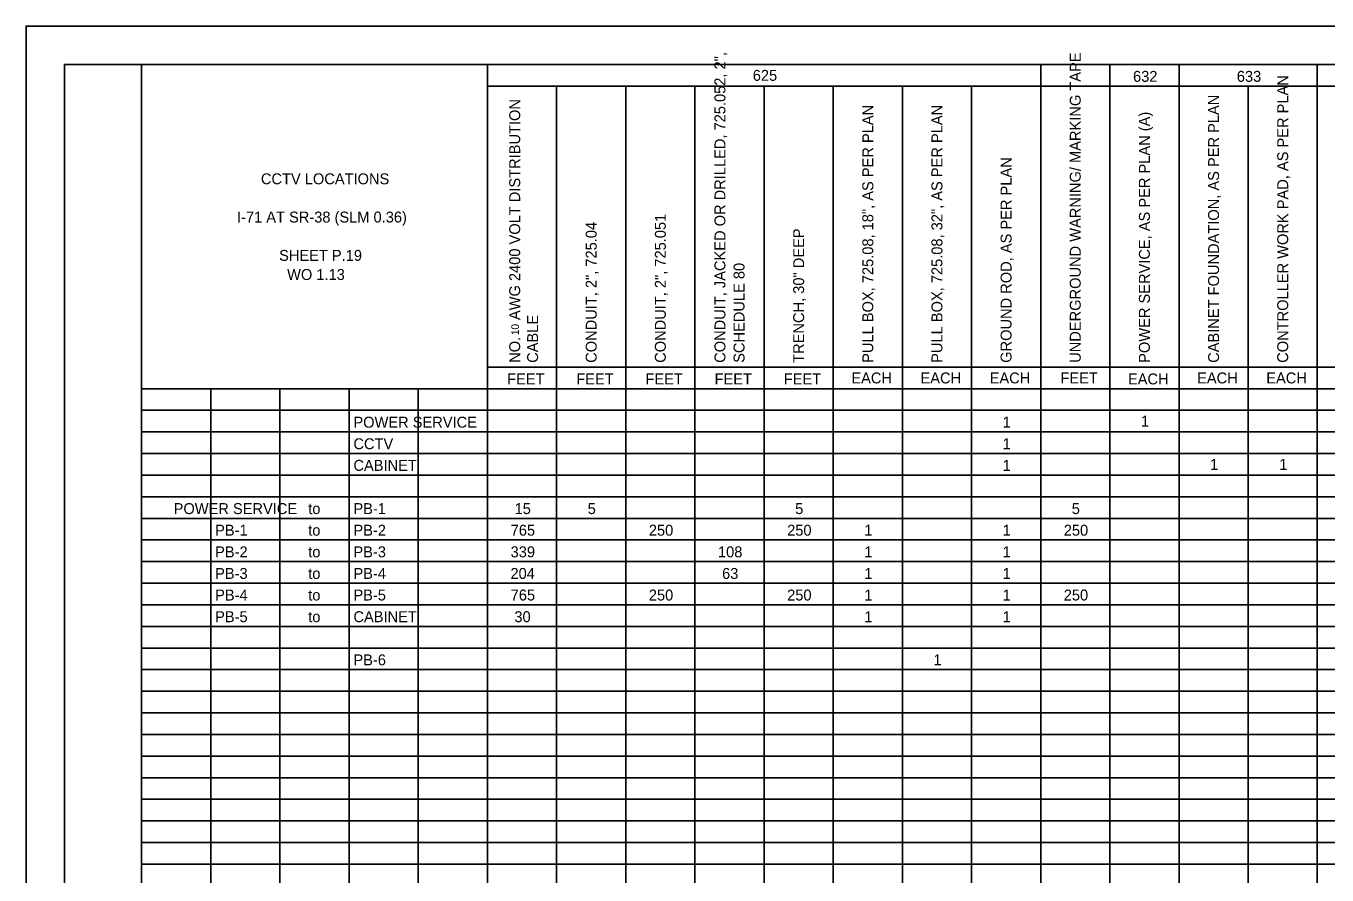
# Model space of a CAD drawing. Extents: x 0 to 34, y 0 to 22.
# Drawn here: x 0 to 16.88, y 10.99 to 22 of the extents above; entities that cross this region are included whole.
import ezdxf

# ---------------------------------------------------------------- set-up
doc = ezdxf.new("R2010")
doc.units = 0
for name, color, linetype in [('SH_Border', 7, 'Continuous'), ('SH_Cut_Line', 7, 'Continuous'), ('SH_Text', 7, 'Continuous')]:
    doc.layers.add(name, color=color, linetype=linetype)

msp = doc.modelspace()

# ---------------------------------------------------------------- linework, layer by layer
at = {"layer": 'SH_Border'}
for points in [[(0.5, 21.5), (1.5, 21.5), (1.5, 0.5), (0.5, 0.5)], [(1.5, 21.5), (33.5, 21.5), (33.5, 0.5), (1.5, 0.5)]]:
    msp.add_lwpolyline(points, close=True, dxfattribs=at)
at = {"layer": 'SH_Cut_Line'}
msp.add_lwpolyline([(0, 0), (34, 0), (34, 22), (0, 22)], close=True, dxfattribs=at)
at = {"layer": 'SH_Text'}
for p, q in [((1.5, 21.5), (32, 21.5)), ((1.5, 21.5), (1.5, 0.756)), ((5.985, 21.5), (5.985, 0.756)), ((13.162, 21.5), (13.162, 0.756)), ((14.059, 21.5), (14.059, 0.756)), ((14.956, 21.5), (14.956, 0.756)), ((16.75, 21.5), (16.75, 0.756)), ((5.985, 21.22), (32, 21.22)), ((6.882, 21.22), (6.882, 0.756)), ((7.779, 21.22), (7.779, 0.756)), ((8.676, 21.22), (8.676, 0.756)), ((9.574, 21.22), (9.574, 0.756)), ((10.471, 21.22), (10.471, 0.756)), ((11.368, 21.22), (11.368, 0.756)), ((12.265, 21.22), (12.265, 0.756)), ((15.853, 21.22), (15.853, 0.756)), ((5.985, 17.575), (32, 17.575)), ((1.5, 17.295), (32, 17.295)), ((1.5, 17.015), (32, 17.015)), ((1.5, 16.734), (32, 16.734)), ((1.5, 16.454), (32, 16.454)), ((1.5, 16.174), (32, 16.174)), ((1.5, 15.893), (32, 15.893)), ((1.5, 15.613), (32, 15.613)), ((1.5, 15.333), (32, 15.333)), ((1.5, 15.052), (32, 15.052)), ((1.5, 14.772), (32, 14.772)), ((1.5, 14.492), (32, 14.492)), ((1.5, 14.211), (32, 14.211)), ((1.5, 13.931), (32, 13.931)), ((1.5, 13.651), (32, 13.651)), ((1.5, 13.37), (32, 13.37)), ((1.5, 13.09), (32, 13.09)), ((1.5, 12.81), (32, 12.81)), ((1.5, 12.529), (32, 12.529)), ((1.5, 12.249), (32, 12.249)), ((1.5, 11.969), (32, 11.969)), ((1.5, 11.688), (32, 11.688)), ((1.5, 11.408), (32, 11.408)), ((1.5, 11.128), (32, 11.128))]:
    msp.add_line(p, q, dxfattribs=at)
for points in [[(1.5, 17.295), (2.397, 17.295), (2.397, 17.015), (1.5, 17.015)], [(2.397, 17.295), (3.294, 17.295), (3.294, 17.015), (2.397, 17.015)], [(3.294, 17.295), (4.191, 17.295), (4.191, 17.015), (3.294, 17.015)], [(4.191, 17.295), (5.088, 17.295), (5.088, 17.015), (4.191, 17.015)], [(5.088, 17.295), (5.985, 17.295), (5.985, 17.015), (5.088, 17.015)], [(1.5, 17.015), (2.397, 17.015), (2.397, 16.734), (1.5, 16.734)], [(2.397, 17.015), (3.294, 17.015), (3.294, 16.734), (2.397, 16.734)], [(3.294, 17.015), (4.191, 17.015), (4.191, 16.734), (3.294, 16.734)], [(4.191, 17.015), (5.088, 17.015), (5.088, 16.734), (4.191, 16.734)], [(5.088, 17.015), (5.985, 17.015), (5.985, 16.734), (5.088, 16.734)], [(1.5, 16.734), (2.397, 16.734), (2.397, 16.454), (1.5, 16.454)], [(2.397, 16.734), (3.294, 16.734), (3.294, 16.454), (2.397, 16.454)], [(3.294, 16.734), (4.191, 16.734), (4.191, 16.454), (3.294, 16.454)], [(4.191, 16.734), (5.088, 16.734), (5.088, 16.454), (4.191, 16.454)], [(5.088, 16.734), (5.985, 16.734), (5.985, 16.454), (5.088, 16.454)], [(1.5, 16.454), (2.397, 16.454), (2.397, 16.174), (1.5, 16.174)], [(2.397, 16.454), (3.294, 16.454), (3.294, 16.174), (2.397, 16.174)], [(3.294, 16.454), (4.191, 16.454), (4.191, 16.174), (3.294, 16.174)], [(4.191, 16.454), (5.088, 16.454), (5.088, 16.174), (4.191, 16.174)], [(5.088, 16.454), (5.985, 16.454), (5.985, 16.174), (5.088, 16.174)], [(1.5, 16.174), (2.397, 16.174), (2.397, 15.893), (1.5, 15.893)], [(2.397, 16.174), (3.294, 16.174), (3.294, 15.893), (2.397, 15.893)], [(3.294, 16.174), (4.191, 16.174), (4.191, 15.893), (3.294, 15.893)], [(4.191, 16.174), (5.088, 16.174), (5.088, 15.893), (4.191, 15.893)], [(5.088, 16.174), (5.985, 16.174), (5.985, 15.893), (5.088, 15.893)], [(1.5, 15.893), (2.397, 15.893), (2.397, 15.613), (1.5, 15.613)], [(2.397, 15.893), (3.294, 15.893), (3.294, 15.613), (2.397, 15.613)], [(3.294, 15.893), (4.191, 15.893), (4.191, 15.613), (3.294, 15.613)], [(4.191, 15.893), (5.088, 15.893), (5.088, 15.613), (4.191, 15.613)], [(5.088, 15.893), (5.985, 15.893), (5.985, 15.613), (5.088, 15.613)], [(1.5, 15.613), (2.397, 15.613), (2.397, 15.333), (1.5, 15.333)], [(2.397, 15.613), (3.294, 15.613), (3.294, 15.333), (2.397, 15.333)], [(3.294, 15.613), (4.191, 15.613), (4.191, 15.333), (3.294, 15.333)], [(4.191, 15.613), (5.088, 15.613), (5.088, 15.333), (4.191, 15.333)], [(5.088, 15.613), (5.985, 15.613), (5.985, 15.333), (5.088, 15.333)], [(1.5, 15.333), (2.397, 15.333), (2.397, 15.052), (1.5, 15.052)], [(2.397, 15.333), (3.294, 15.333), (3.294, 15.052), (2.397, 15.052)], [(3.294, 15.333), (4.191, 15.333), (4.191, 15.052), (3.294, 15.052)], [(4.191, 15.333), (5.088, 15.333), (5.088, 15.052), (4.191, 15.052)], [(5.088, 15.333), (5.985, 15.333), (5.985, 15.052), (5.088, 15.052)], [(1.5, 15.052), (2.397, 15.052), (2.397, 14.772), (1.5, 14.772)], [(2.397, 15.052), (3.294, 15.052), (3.294, 14.772), (2.397, 14.772)], [(3.294, 15.052), (4.191, 15.052), (4.191, 14.772), (3.294, 14.772)], [(4.191, 15.052), (5.088, 15.052), (5.088, 14.772), (4.191, 14.772)], [(5.088, 15.052), (5.985, 15.052), (5.985, 14.772), (5.088, 14.772)], [(1.5, 14.772), (2.397, 14.772), (2.397, 14.492), (1.5, 14.492)], [(2.397, 14.772), (3.294, 14.772), (3.294, 14.492), (2.397, 14.492)], [(3.294, 14.772), (4.191, 14.772), (4.191, 14.492), (3.294, 14.492)], [(4.191, 14.772), (5.088, 14.772), (5.088, 14.492), (4.191, 14.492)], [(5.088, 14.772), (5.985, 14.772), (5.985, 14.492), (5.088, 14.492)], [(1.5, 14.492), (2.397, 14.492), (2.397, 14.211), (1.5, 14.211)], [(2.397, 14.492), (3.294, 14.492), (3.294, 14.211), (2.397, 14.211)], [(3.294, 14.492), (4.191, 14.492), (4.191, 14.211), (3.294, 14.211)], [(4.191, 14.492), (5.088, 14.492), (5.088, 14.211), (4.191, 14.211)], [(5.088, 14.492), (5.985, 14.492), (5.985, 14.211), (5.088, 14.211)], [(1.5, 14.211), (2.397, 14.211), (2.397, 13.931), (1.5, 13.931)], [(2.397, 14.211), (3.294, 14.211), (3.294, 13.931), (2.397, 13.931)], [(3.294, 14.211), (4.191, 14.211), (4.191, 13.931), (3.294, 13.931)], [(4.191, 14.211), (5.088, 14.211), (5.088, 13.931), (4.191, 13.931)], [(5.088, 14.211), (5.985, 14.211), (5.985, 13.931), (5.088, 13.931)], [(1.5, 13.931), (2.397, 13.931), (2.397, 13.651), (1.5, 13.651)], [(2.397, 13.931), (3.294, 13.931), (3.294, 13.651), (2.397, 13.651)], [(3.294, 13.931), (4.191, 13.931), (4.191, 13.651), (3.294, 13.651)], [(4.191, 13.931), (5.088, 13.931), (5.088, 13.651), (4.191, 13.651)], [(5.088, 13.931), (5.985, 13.931), (5.985, 13.651), (5.088, 13.651)], [(1.5, 13.651), (2.397, 13.651), (2.397, 13.37), (1.5, 13.37)], [(2.397, 13.651), (3.294, 13.651), (3.294, 13.37), (2.397, 13.37)], [(3.294, 13.651), (4.191, 13.651), (4.191, 13.37), (3.294, 13.37)], [(4.191, 13.651), (5.088, 13.651), (5.088, 13.37), (4.191, 13.37)], [(5.088, 13.651), (5.985, 13.651), (5.985, 13.37), (5.088, 13.37)], [(1.5, 13.37), (2.397, 13.37), (2.397, 13.09), (1.5, 13.09)], [(2.397, 13.37), (3.294, 13.37), (3.294, 13.09), (2.397, 13.09)], [(3.294, 13.37), (4.191, 13.37), (4.191, 13.09), (3.294, 13.09)], [(4.191, 13.37), (5.088, 13.37), (5.088, 13.09), (4.191, 13.09)], [(5.088, 13.37), (5.985, 13.37), (5.985, 13.09), (5.088, 13.09)], [(1.5, 13.09), (2.397, 13.09), (2.397, 12.81), (1.5, 12.81)], [(2.397, 13.09), (3.294, 13.09), (3.294, 12.81), (2.397, 12.81)], [(3.294, 13.09), (4.191, 13.09), (4.191, 12.81), (3.294, 12.81)], [(4.191, 13.09), (5.088, 13.09), (5.088, 12.81), (4.191, 12.81)], [(5.088, 13.09), (5.985, 13.09), (5.985, 12.81), (5.088, 12.81)], [(1.5, 12.81), (2.397, 12.81), (2.397, 12.529), (1.5, 12.529)], [(2.397, 12.81), (3.294, 12.81), (3.294, 12.529), (2.397, 12.529)], [(3.294, 12.81), (4.191, 12.81), (4.191, 12.529), (3.294, 12.529)], [(4.191, 12.81), (5.088, 12.81), (5.088, 12.529), (4.191, 12.529)], [(5.088, 12.81), (5.985, 12.81), (5.985, 12.529), (5.088, 12.529)], [(1.5, 12.529), (2.397, 12.529), (2.397, 12.249), (1.5, 12.249)], [(2.397, 12.529), (3.294, 12.529), (3.294, 12.249), (2.397, 12.249)], [(3.294, 12.529), (4.191, 12.529), (4.191, 12.249), (3.294, 12.249)], [(4.191, 12.529), (5.088, 12.529), (5.088, 12.249), (4.191, 12.249)], [(5.088, 12.529), (5.985, 12.529), (5.985, 12.249), (5.088, 12.249)], [(1.5, 12.249), (2.397, 12.249), (2.397, 11.969), (1.5, 11.969)], [(2.397, 12.249), (3.294, 12.249), (3.294, 11.969), (2.397, 11.969)], [(3.294, 12.249), (4.191, 12.249), (4.191, 11.969), (3.294, 11.969)], [(4.191, 12.249), (5.088, 12.249), (5.088, 11.969), (4.191, 11.969)], [(5.088, 12.249), (5.985, 12.249), (5.985, 11.969), (5.088, 11.969)], [(1.5, 11.969), (2.397, 11.969), (2.397, 11.688), (1.5, 11.688)], [(2.397, 11.969), (3.294, 11.969), (3.294, 11.688), (2.397, 11.688)], [(3.294, 11.969), (4.191, 11.969), (4.191, 11.688), (3.294, 11.688)], [(4.191, 11.969), (5.088, 11.969), (5.088, 11.688), (4.191, 11.688)], [(5.088, 11.969), (5.985, 11.969), (5.985, 11.688), (5.088, 11.688)], [(1.5, 11.688), (2.397, 11.688), (2.397, 11.408), (1.5, 11.408)], [(2.397, 11.688), (3.294, 11.688), (3.294, 11.408), (2.397, 11.408)], [(3.294, 11.688), (4.191, 11.688), (4.191, 11.408), (3.294, 11.408)], [(4.191, 11.688), (5.088, 11.688), (5.088, 11.408), (4.191, 11.408)], [(5.088, 11.688), (5.985, 11.688), (5.985, 11.408), (5.088, 11.408)], [(1.5, 11.408), (2.397, 11.408), (2.397, 11.128), (1.5, 11.128)], [(2.397, 11.408), (3.294, 11.408), (3.294, 11.128), (2.397, 11.128)], [(3.294, 11.408), (4.191, 11.408), (4.191, 11.128), (3.294, 11.128)], [(4.191, 11.408), (5.088, 11.408), (5.088, 11.128), (4.191, 11.128)], [(5.088, 11.408), (5.985, 11.408), (5.985, 11.128), (5.088, 11.128)], [(1.5, 11.128), (2.397, 11.128), (2.397, 10.847), (1.5, 10.847)], [(2.397, 11.128), (3.294, 11.128), (3.294, 10.847), (2.397, 10.847)], [(3.294, 11.128), (4.191, 11.128), (4.191, 10.847), (3.294, 10.847)], [(4.191, 11.128), (5.088, 11.128), (5.088, 10.847), (4.191, 10.847)], [(5.088, 11.128), (5.985, 11.128), (5.985, 10.847), (5.088, 10.847)]]:
    msp.add_lwpolyline(points, close=True, dxfattribs=at)

# ---------------------------------------------------------------- texts
for s, height, p in [('CONDUIT, JACKED OR DRILLED, 725.052, 2", ', 0.14185, (9.072, 17.631)), ('UNDERGROUND WARNING/ MARKING TAPE', 0.14185, (13.681, 17.631)), ('CONTROLLER WORK PAD, AS PER PLAN', 0.14185, (16.372, 17.631)), (' AWG 2400 VOLT DISTRIBUTION ', 0.14185, (6.41, 18.133)), ('PULL BOX, 725.08, 18", AS PER PLAN', 0.14185, (10.99, 17.631)), ('PULL BOX, 725.08, 32", AS PER PLAN', 0.14185, (11.887, 17.631)), ('CABINET FOUNDATION, AS PER PLAN', 0.14185, (15.475, 17.631)), ('POWER SERVICE, AS PER PLAN (A)', 0.14185, (14.578, 17.631)), ('GROUND ROD, AS PER PLAN', 0.14185, (12.784, 17.631)), ('CONDUIT, 2", 725.04', 0.14185, (7.402, 17.631)), ('CONDUIT, 2", 725.051', 0.14185, (8.299, 17.631)), ('TRENCH, 30" DEEP', 0.14185, (10.093, 17.631)), ('SCHEDULE 80', 0.14185, (9.32, 17.631)), ('CABLE', 0.1418, (6.642, 17.631)), ('0', 0.0993, (6.394, 18.062)), ('1', 0.0993, (6.394, 17.991)), ('NO. ', 0.1418, (6.41, 17.631))]:
    msp.add_text(s, height=height, rotation=90, dxfattribs=at).set_placement(p)
for s, height, p in [('625', 0.1418, (9.427, 21.289)), ('632', 0.1418, (14.36, 21.276)), ('633', 0.1418, (15.706, 21.276)), ('CCTV LOCATIONS', 0.14185, (3.047, 19.947)), ('I-71 AT SR-38 (SLM 0.36)', 0.14185, (2.737, 19.451)), ('SHEET P.19', 0.1418, (3.283, 18.954)), ('WO 1.13', 0.1418, (3.387, 18.706)), ('FEET', 0.1418, (6.241, 17.351)), ('FEET', 0.1418, (7.138, 17.351)), ('FEET', 0.1418, (8.035, 17.351)), ('FEET', 0.1418, (8.932, 17.351)), ('FEET', 0.1418, (9.829, 17.351)), ('EACH', 0.1418, (10.706, 17.364)), ('EACH', 0.1418, (11.603, 17.364)), ('EACH', 0.1418, (12.5, 17.364)), ('FEET', 0.1418, (13.418, 17.364)), ('EACH', 0.1418, (14.294, 17.351)), ('EACH', 0.1418, (15.191, 17.364)), ('EACH', 0.1418, (16.088, 17.364)), ('POWER SERVICE', 0.14185, (4.247, 16.79)), ('1', 0.142, (12.668, 16.79)), ('1', 0.142, (14.462, 16.804)), ('CCTV', 0.1418, (4.247, 16.51)), ('1', 0.142, (12.668, 16.51)), ('CABINET', 0.1418, (4.247, 16.23)), ('1', 0.142, (12.668, 16.23)), ('1', 0.142, (15.359, 16.243)), ('1', 0.142, (16.256, 16.243)), ('POWER SERVICE', 0.14185, (1.915, 15.669)), ('to', 0.1418, (3.661, 15.669)), ('PB-1', 0.1418, (4.247, 15.669)), ('15', 0.1418, (6.338, 15.669)), ('5', 0.142, (7.286, 15.669)), ('5', 0.142, (9.977, 15.669)), ('5', 0.142, (13.565, 15.669)), ('PB-1', 0.1418, (2.453, 15.389)), ('PB-2', 0.1418, (4.247, 15.389)), ('765', 0.1418, (6.287, 15.389)), ('250', 0.1418, (8.079, 15.389)), ('250', 0.1418, (9.873, 15.389)), ('1', 0.142, (10.874, 15.389)), ('1', 0.142, (12.668, 15.389)), ('250', 0.1418, (13.461, 15.389)), ('to', 0.1418, (3.661, 15.389)), ('PB-2', 0.1418, (2.453, 15.108)), ('to', 0.1418, (3.661, 15.108)), ('PB-3', 0.1418, (4.247, 15.108)), ('339', 0.1418, (6.286, 15.108)), ('108', 0.1418, (8.976, 15.108)), ('1', 0.142, (10.874, 15.108)), ('1', 0.142, (12.668, 15.108)), ('PB-3', 0.1418, (2.453, 14.828)), ('to', 0.1418, (3.661, 14.828)), ('PB-4', 0.1418, (4.247, 14.828)), ('204', 0.1418, (6.284, 14.828)), ('63', 0.1418, (9.029, 14.828)), ('1', 0.142, (10.874, 14.828)), ('1', 0.142, (12.668, 14.828)), ('PB-4', 0.1418, (2.453, 14.548)), ('PB-5', 0.1418, (4.247, 14.548)), ('765', 0.1418, (6.287, 14.548)), ('250', 0.1418, (8.079, 14.548)), ('250', 0.1418, (9.873, 14.548)), ('1', 0.142, (10.874, 14.548)), ('1', 0.142, (12.668, 14.548)), ('250', 0.1418, (13.461, 14.548)), ('to', 0.1418, (3.661, 14.548)), ('PB-5', 0.1418, (2.453, 14.267)), ('to', 0.1418, (3.661, 14.267)), ('CABINET', 0.1418, (4.247, 14.267)), ('30', 0.1418, (6.335, 14.267)), ('1', 0.142, (10.874, 14.267)), ('1', 0.142, (12.668, 14.267)), ('PB-6', 0.1418, (4.247, 13.707)), ('1', 0.142, (11.771, 13.707))]:
    msp.add_text(s, height=height, dxfattribs=at).set_placement(p)

doc.saveas('drawing.dxf')
